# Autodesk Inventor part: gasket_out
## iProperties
Created: 2007-12
Part Number: gasket_out
Document SubType Name: Modeling
Designer: Arthur Queval
Author: Arthur Queval
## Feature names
1. Extrusion1
2. Fillet1
3. Extrusion2
